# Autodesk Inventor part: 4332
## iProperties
Author: Administrator
Shininess: 50.0
PropertySet Name: _Private Model Information
Created: 2001-08
Part Number: 4332
Document SubType Name: Modeling
Designer: Administrator
Material: Aluminum-6061
Description: Inside Gusset Corner Braket, 4332
Control State: 0
Master: False
Checked Out: False
PropertySet Name: Design Tracking Control
Density: 2.7099999999999995
Volumn: 6.057682005849042
Area: 35.370051087210165
PropertySet Name: Model Information
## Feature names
1. Extrusion1
2. Extrusion2
3. Extrusion3
4. Extrusion4
5. Extrusion5
6. Extrusion6
